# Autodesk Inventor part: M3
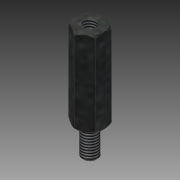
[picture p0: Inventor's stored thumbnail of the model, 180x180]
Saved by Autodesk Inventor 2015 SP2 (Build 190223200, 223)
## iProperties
Created: 2012-08
Part Number: M3
Material: Stahl
Document SubType Name: Modeling
Designer: rYan
Density: 7.85 g/cm^3
Mass: 1.74537 g
Surface Area: 3.04272 cm^2
Volume: 0.22234 cm^3
Appearance: Platte
Author: rYan
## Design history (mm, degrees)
derived "Abstandsbolzen Typ B.ipt"
feature "Volumenkörper1::Abstandsbolzen Typ B.ipt"
tag "Bezeichnung1"
node "Volumenkörper1"
other parameters: "SW" = 5.5, "L" = 17, "d2" = 0, "l_" = 7, "d9" = 118 deg, "GA_" = 3, "A_" = 6, "d13" = 0, "d17" = 0.25, "d20" = 45 deg
